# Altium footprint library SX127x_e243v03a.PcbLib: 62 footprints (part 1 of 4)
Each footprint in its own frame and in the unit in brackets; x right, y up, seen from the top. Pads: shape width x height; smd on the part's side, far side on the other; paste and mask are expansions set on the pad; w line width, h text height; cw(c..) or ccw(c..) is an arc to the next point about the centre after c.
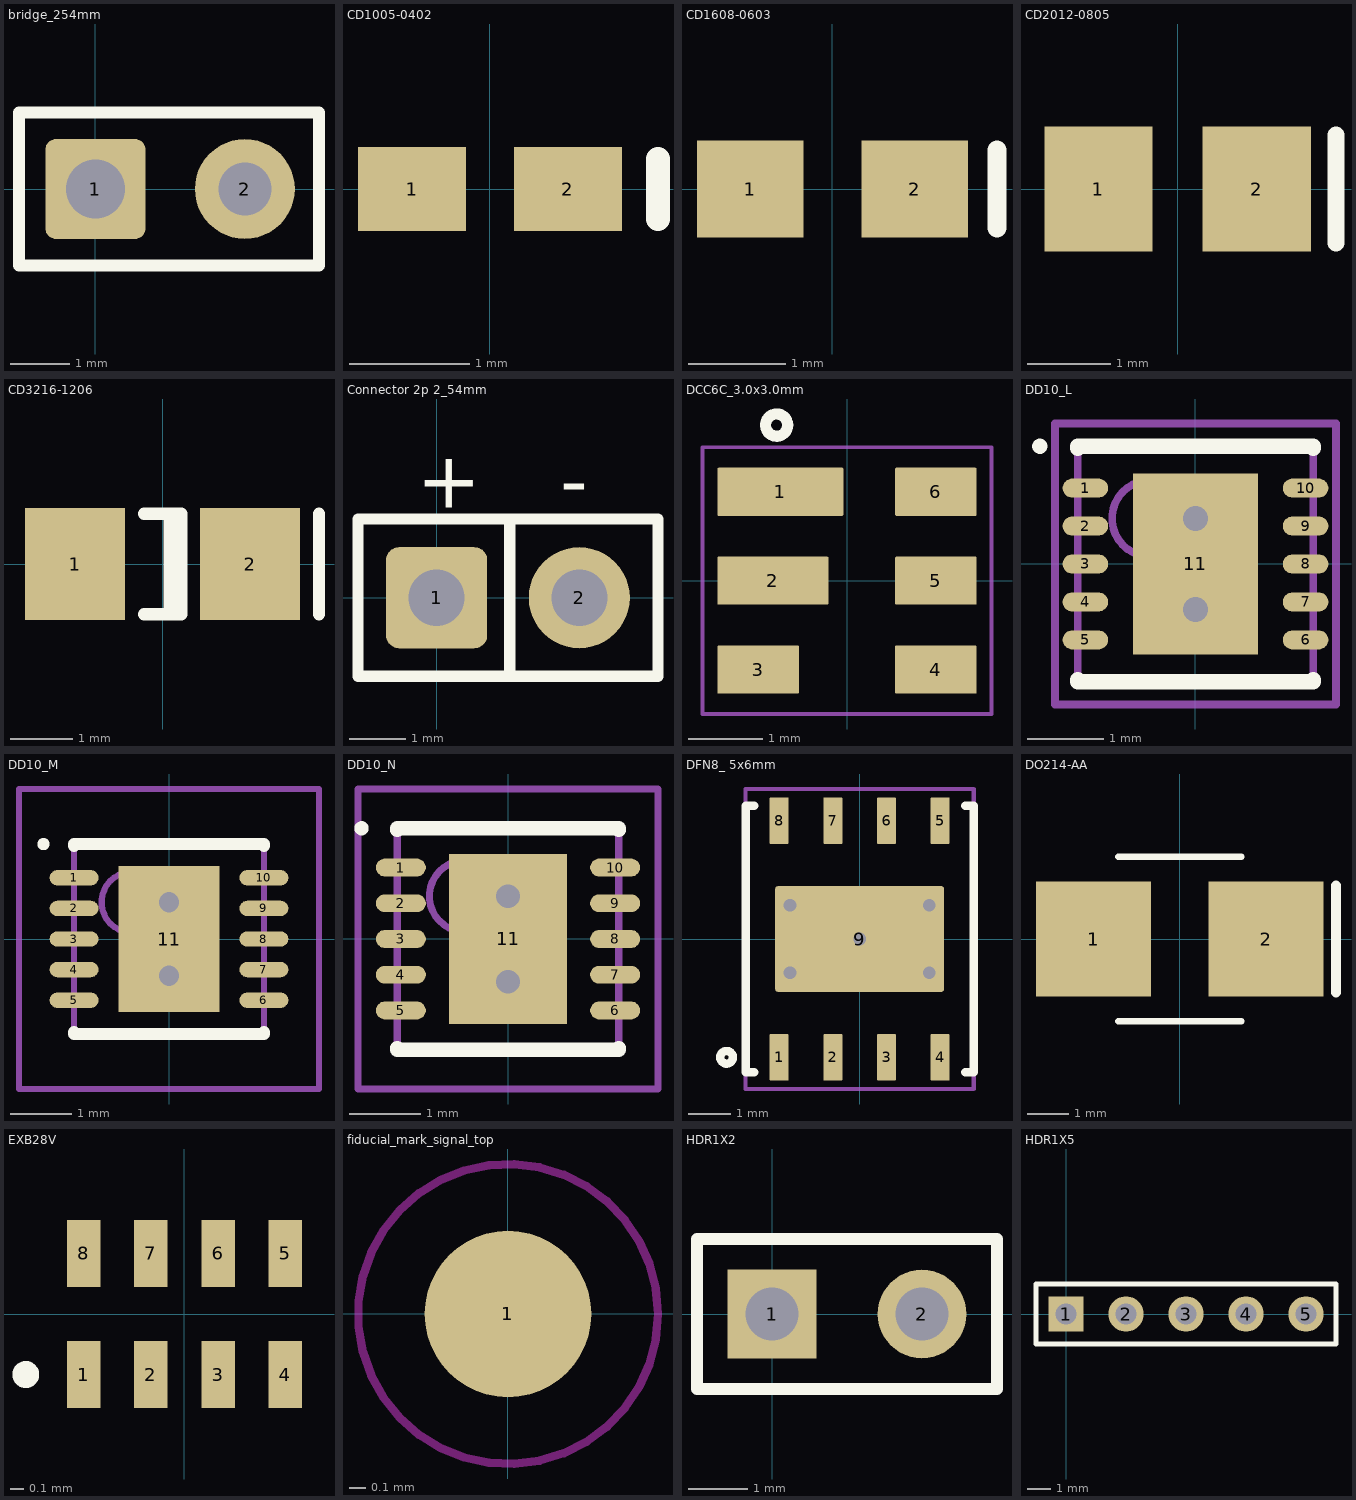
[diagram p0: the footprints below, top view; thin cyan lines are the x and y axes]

## bridge_254mm [mm] "Generic Bridge 2.54mm, 2 Leads 0.9mm;"
height 1
pads (2):
  rrect20% 1.7x1.7 hole 1 paste+0 mask+0.05: 1(0,0)
  round 1.7 hole 0.9 paste+0 mask+0.05: 2(2.54,0)
Top Overlay:
  lines w0.2: -1.3,-1.3 3.8,-1.3 3.8,1.3 -1.3,1.3 -1.3,-1.3

## CD1005-0402 [mm] "Chip Diode; Body 1.0 x 0.5 mm (LxW typ)"
height 0.6
pads (2):
  rect 0.9x0.7 smd mask+0.05: 1(-0.65,0) 2(0.65,0)
Top Overlay:
  lines w0.2: 1.4,-0.25 1.4,0.25

## CD1608-0603 [mm] "Chip Diode; Body 1.6 x 0.8 mm (LxW typ)"
height 0.85
pads (2):
  rect 1.1x1 smd mask+0.05: 1(-0.85,0) 2(0.85,0)
Top Overlay:
  lines w0.2: 1.7,-0.4 1.7,0.4

## CD2012-0805 [mm] "Chip Diode; Body 2.0 x 1.3 mm (LxW typ)"
height 1.1
pads (2):
  rect 1.3x1.5 smd mask+0.05: 1(-0.95,0) 2(0.95,0)
Top Overlay:
  lines w0.2: 1.9,-0.65 1.9,0.65

## CD3216-1206 [mm] "Chip Diode; Body 3.2 x 1.6 mm (LxW typ)"
height 1.35
pads (2):
  rect 1.6x1.8 smd mask+0.05: 1(-1.4,0) 2(1.4,0)
Top Overlay:
  lines w0.2: -0.3,-0.8 0.3,-0.8 0.3,0.8 -0.3,0.8 ; 0.11,-0.8 0.11,0.8 ; 2.5,-0.8 2.5,0.8

## Connector 2p 2_54mm [mm] "Generic connector 2.54mm, 2 Leads 1mm;"
height 1
pads (2):
  rrect25% 1.8x1.8 hole 1 paste+0 mask+0.05: 1(0,0)
  round 1.8 hole 1 paste+0 mask+0.05: 2(2.54,0)
Top Overlay:
  lines w0.2: 1.3,-1.4 1.3,1.4 ; -1.4,-1.4 -1.4,1.4 3.94,1.4 3.94,-1.4 -1.4,-1.4
  text "-" at 2.2,1.6 h1
  text "+" at -0.35,1.6 h1

## DCC6C_3.0x3.0mm [mm] "DCC6C footprint, 3.0x3.0mm"
height 1.1
pads (6):
  rrect5% 1.7x0.65 smd mask+0.05: 1(-0.9,1.2)
  rrect5% 1.5x0.65 smd mask+0.05: 2(-1,0)
  rrect5% 1.1x0.65 smd mask+0.05: 3(-1.2,-1.2) 4(1.2,-1.2) 5(1.2,0) 6(1.2,1.2)
Top Overlay:
  circle w0.15: c-0.95,2.1 r0.15
Mechanical 15:
  lines w0.05: -1.95,-1.8 1.95,-1.8 1.95,1.8 -1.95,1.8 -1.95,-1.8
3D body: height 1, standoff 0, extent -1.5,-1.5 1.5,1.5

## DD10_L [mm] "SON, 10-Leads, Body 3x3 mm, Pitch 0.5mm, IPC High Density"
height 0.8
pads (11):
  oval 0.6x0.25 smd: 1(-1.45,1) 2(-1.45,0.5) 3(-1.45,0) 4(-1.45,-0.5) 5(-1.45,-1) 6(1.45,-1) 7(1.45,-0.5) 8(1.45,0) 9(1.45,0.5) 10(1.45,1)
  rect 1.65x2.38 smd: 11(0,0)
via 0,0.6 diameter 0.66 hole 0.33
via 0,-0.6 diameter 0.66 hole 0.33
Top Overlay:
  circle w0.1: c-2.05,1.55 r0.05
  lines w0.2: -1.55,-1.525 -1.55,-1.55 1.55,-1.55 1.55,-1.525 ; -1.55,1.525 -1.55,1.55 1.55,1.55 1.55,1.525
Mechanical 13:
  circle w0.1: c-0.6,0.6 r0.5
  lines w0.1: -1.55,-1.55 1.55,-1.55 1.55,1.55 -1.55,1.55 -1.55,-1.55
Mechanical 15:
  lines w0.1: -0.5,0 0.5,0 ; 0,-0.5 0,0.5 ; -1.85,-1.85 1.85,-1.85 1.85,1.85 -1.85,1.85 -1.85,-1.85
3D body: height 0.8, standoff 0, extent -1.55,-1.55 1.55,1.55

## DD10_M [mm] "SON, 10-Leads, Body 3x3 mm, Pitch 0.5mm, IPC Low Density"
height 0.8
pads (11):
  oval 0.8x0.25 smd: 1(-1.55,1) 2(-1.55,0.5) 3(-1.55,0) 4(-1.55,-0.5) 5(-1.55,-1) 6(1.55,-1) 7(1.55,-0.5) 8(1.55,0) 9(1.55,0.5) 10(1.55,1)
  rect 1.65x2.38 smd: 11(0,0)
via 0,0.6 diameter 0.66 hole 0.33
via 0,-0.6 diameter 0.66 hole 0.33
Top Overlay:
  circle w0.1: c-2.05,1.55 r0.05
  lines w0.2: -1.55,-1.525 -1.55,-1.55 1.55,-1.55 1.55,-1.525 ; -1.55,1.525 -1.55,1.55 1.55,1.55 1.55,1.525
Mechanical 13:
  circle w0.1: c-0.6,0.6 r0.5
  lines w0.1: -1.55,-1.55 1.55,-1.55 1.55,1.55 -1.55,1.55 -1.55,-1.55
Mechanical 15:
  lines w0.1: -0.5,0 0.5,0 ; 0,-0.5 0,0.5 ; -2.45,-2.45 2.45,-2.45 2.45,2.45 -2.45,2.45 -2.45,-2.45
3D body: height 0.8, standoff 0, extent -1.55,-1.55 1.55,1.55

## DD10_N [mm] "SON, 10-Leads, Body 3x3 mm, Pitch 0.5mm, IPC Medium Density"
height 0.8
pads (11):
  oval 0.7x0.25 smd: 1(-1.5,1) 2(-1.5,0.5) 3(-1.5,0) 4(-1.5,-0.5) 5(-1.5,-1) 6(1.5,-1) 7(1.5,-0.5) 8(1.5,0) 9(1.5,0.5) 10(1.5,1)
  rect 1.65x2.38 smd: 11(0,0)
via 0,-0.6 diameter 0.66 hole 0.33
via 0,0.6 diameter 0.66 hole 0.33
Top Overlay:
  circle w0.1: c-2.05,1.55 r0.05
  lines w0.2: -1.55,-1.525 -1.55,-1.55 1.55,-1.55 1.55,-1.525 ; -1.55,1.525 -1.55,1.55 1.55,1.55 1.55,1.525
Mechanical 13:
  circle w0.1: c-0.6,0.6 r0.5
  lines w0.1: -1.55,-1.55 -1.55,1.55 1.55,1.55 1.55,-1.55 -1.55,-1.55
Mechanical 15:
  lines w0.1: -0.5,0 0.5,0 ; 0,-0.5 0,0.5 ; -2.1,-2.1 -2.1,2.1 2.1,2.1 2.1,-2.1 -2.1,-2.1
3D body: height 0.8, standoff 0, extent -1.55,-1.55 1.55,1.55

## DFN8_ 5x6mm [mm] "8 Leads, Body 5x6mm, pitch 1.27mm, DFN8"
height 0.9
pads (9):
  rrect10% 0.45x1.1 smd paste+0 mask+0.05: 1(-1.905,-2.8) 2(-0.635,-2.8) 3(0.635,-2.8) 4(1.905,-2.8) 5(1.905,2.8) 6(0.635,2.8) 7(-0.635,2.8) 8(-1.905,2.8)
  rrect5% 4x2.5 smd paste+0 mask+0.05: 9(0,0)
via -1.65,0.8 diameter 0.6 hole 0.3
via -1.65,-0.8 diameter 0.6 hole 0.3
via 0,0 diameter 0.6 hole 0.3
via 1.65,-0.8 diameter 0.6 hole 0.3
via 1.65,0.8 diameter 0.6 hole 0.3
Top Overlay:
  circle w0.2: c-3.15,-2.8 r0.15
  lines w0.2: -2.5,-3.15 -2.7,-3.15 -2.7,3.15 -2.5,3.15 ; 2.5,-3.15 2.7,-3.15 2.7,3.15 2.5,3.15
Top Paste:
  rectangle: -1.4,-0.8 1.4,0.8
Mechanical 15:
  lines w0.1: -2.7,-3.55 2.7,-3.55 2.7,3.55 -2.7,3.55 -2.7,-3.55
3D body: height 12, standoff 0, extent -2.5,-3 2.5,3

## DO214-AA [mm] "Chip Diode; Body 4.3 x3.6mm (LxW typ)"
height 1
pads (2):
  rect 2.8x2.8 smd mask+0.05: 1(-2.1,0) 2(2.1,0)
Top Overlay:
  lines w0.15: -1.5,-2 1.5,-2 ; -1.5,2 1.5,2
  lines w0.25: 3.8,-1.3 3.8,1.3

## EXB28V [mm] "Chip Resistor Array, (0402x4); SM; 8 Leads; Body 2.10 x 1.10 mm (LxW max)"
height 0.45
pads (8):
  rect 0.25x0.5 smd mask+0.05: 1(-0.75,-0.45) 2(-0.25,-0.45) 3(0.25,-0.45) 4(0.75,-0.45) 5(0.75,0.45) 6(0.25,0.45) 7(-0.25,0.45) 8(-0.75,0.45)
Top Overlay:
  circle w0.1: c-1.18,-0.45 r0.05

## fiducial_mark_signal_top [mm] "Fiducial mark for automatic assembly"
height 1
pads (1):
  round 1 smd paste-2 mask+0.5: 1(0,0)
Top Layer keep-out:
  circle w0.05: c0,0 r0.9

## HDR1X2 [mm] "Connector; Header; 2 Position"
pads (2):
  rect 1.5x1.5 hole 0.9: 1(0,0)
  round 1.5 hole 0.9: 2(2.54,0)
Top Overlay:
  lines w0.2: -1.27,-1.27 3.81,-1.27 3.81,1.27 -1.27,1.27 -1.27,-1.27

## HDR1X5 [mm] "Connector; Header; 5 Position"
pads (5):
  rect 1.5x1.5 hole 0.9: 1(0,0)
  round 1.5 hole 0.9: 2(2.54,0) 3(5.08,0) 4(7.62,0) 5(10.16,0)
Top Overlay:
  lines w0.2: -1.27,-1.27 11.43,-1.27 11.43,1.27 -1.27,1.27 -1.27,-1.27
